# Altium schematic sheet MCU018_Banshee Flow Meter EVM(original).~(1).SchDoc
size 431 x 279 mm; Date: Not shown in title block; ApprovedBy: Not shown in title block; CheckedBy: Not shown in title block; Author: Not shown in title block; CompanyName: Not shown in title block; Engineer: Not shown in title block; Organization: Not shown in title block; Address1: Not shown in title block; Address2: Not shown in title block; Address3: Not shown in title block; Address4: Not shown in title block; DocumentNumber: 1; Revision: Use project parameter SCH_Rev; SheetNumber: 1; SheetTotal: 6; PageSetup: Record=PageOptions¦CenterHorizontal=True¦CenterVertical=True¦PrintScale=1.00¦XCorrection=1.00¦YCorrection=1.00¦PrintKind=0¦BorderSize=5000000¦LeftOffset=0¦BottomOffset=0¦Orientation=2¦PaperLength=1000¦PaperWidth=1000¦Scale=100¦PaperSource=15¦PrintQuality=600¦MediaType=1¦DitherType=10¦PaperKind=Letter¦PrintScaleMode=1
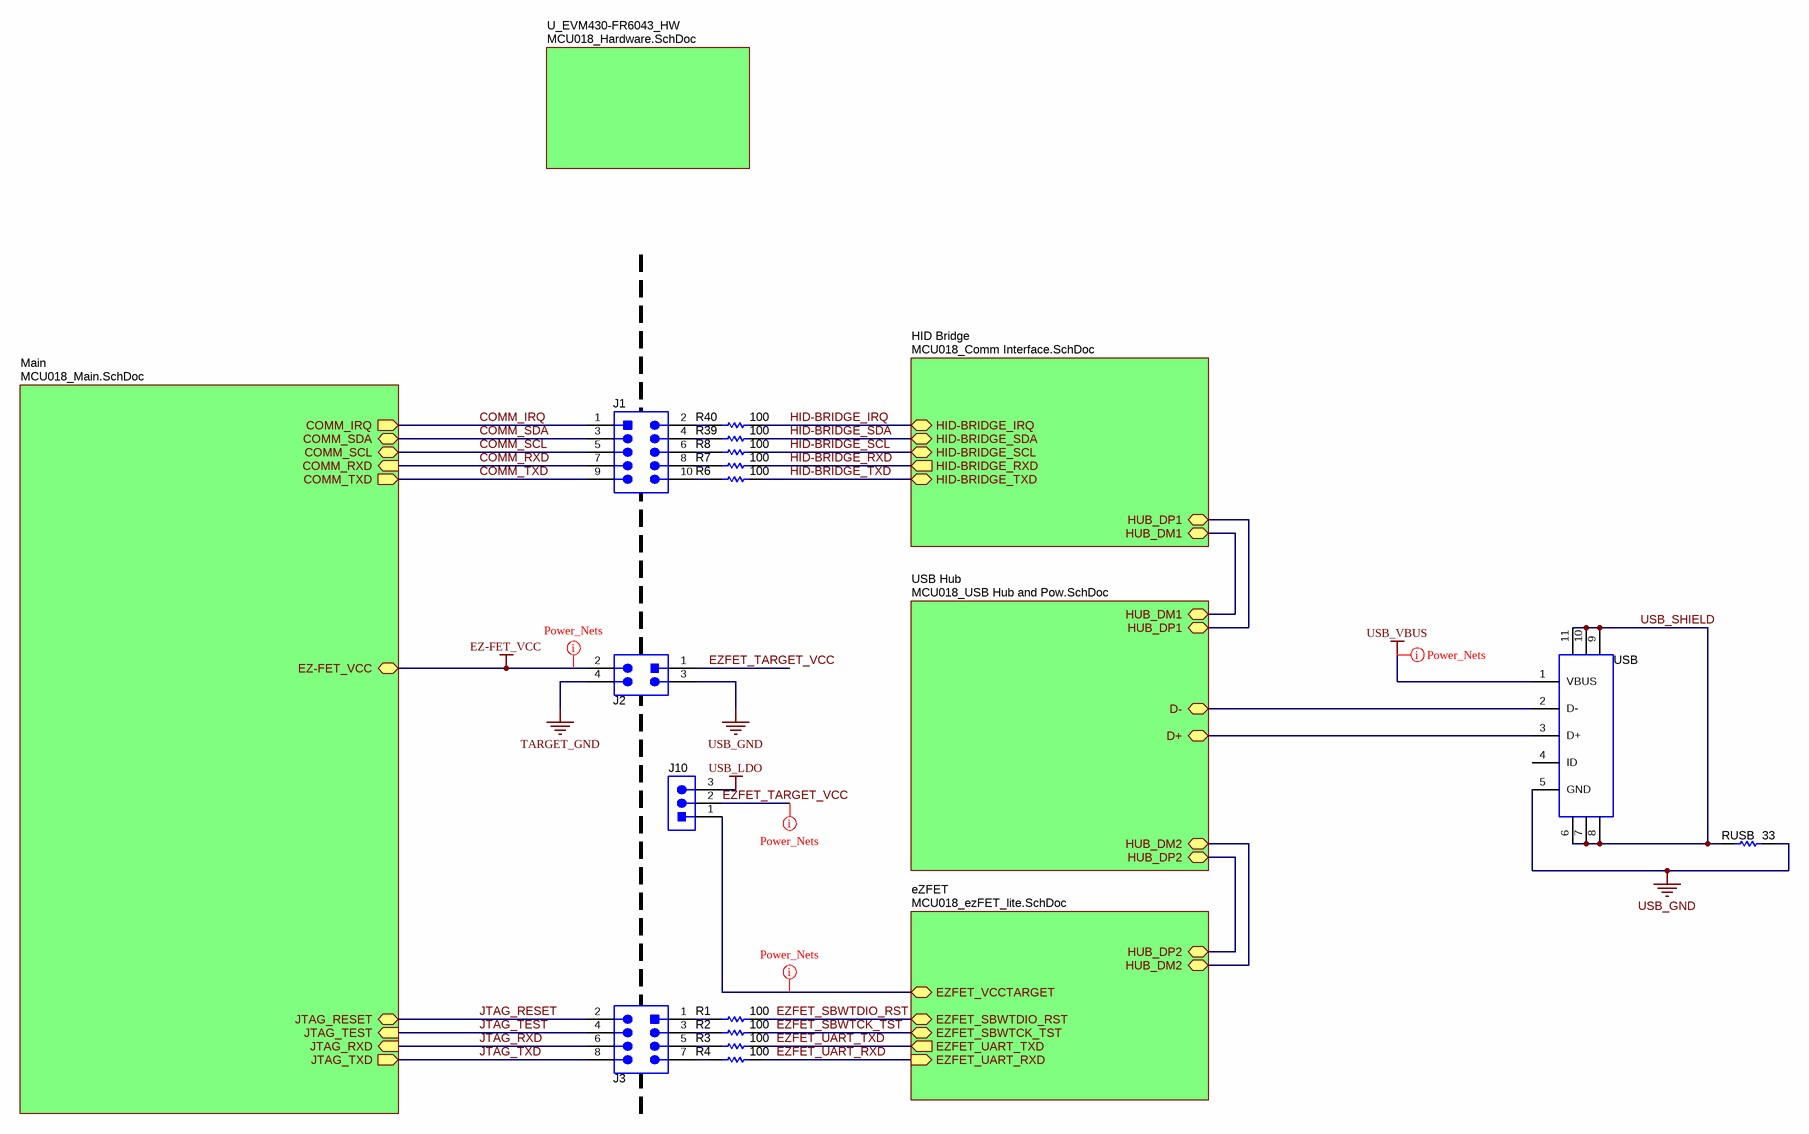
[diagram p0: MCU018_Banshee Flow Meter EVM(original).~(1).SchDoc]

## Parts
J1  61301021121  [WURTH_61301021121]  (value not drawn)
J2  PBC02DAAN  [Sullins_PxC02DAAN]  (value not drawn)
J3  PEC04DAAN  [CONN_PEC04DAAN]  (value not drawn)
J10  61300311121  [WURTH_61300311121]  (value not drawn)
R1  ValueDisplayed: 100  [0402S]  (hidden comment: CRCW0402100RJNED)
R2  ValueDisplayed: 100  [0402S]  (hidden comment: CRCW0402100RJNED)
R3  ValueDisplayed: 100  [0402S]  (hidden comment: CRCW0402100RJNED)
R4  ValueDisplayed: 100  [0402S]  (hidden comment: CRCW0402100RJNED)
R6  ValueDisplayed: 100  [0402S]  (hidden comment: CRCW0402100RJNED)
R7  ValueDisplayed: 100  [0402S]  (hidden comment: CRCW0402100RJNED)
R8  ValueDisplayed: 100  [0402S]  (hidden comment: CRCW0402100RJNED)
R39  ValueDisplayed: 100  [0402S]  (hidden comment: CRCW0402100RJNED)
R40  ValueDisplayed: 100  [0402S]  (hidden comment: CRCW0402100RJNED)
RUSB  value 33  [0402S]  (hidden comment: CRCW040233R0JNED)
USB  1051640001  [Molex_1051640001]  (value not drawn)

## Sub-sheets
eZFET = MCU018_ezFET_lite.SchDoc: EZFET_VCCTARGET, EZFET_SBWTDIO_RST, EZFET_SBWTCK_TST, EZFET_UART_TXD, EZFET_UART_RXD, HUB_DP2, HUB_DM2
HID Bridge = MCU018_Comm Interface.SchDoc: HID-BRIDGE_TXD, HID-BRIDGE_RXD, HID-BRIDGE_SCL, HID-BRIDGE_SDA, HID-BRIDGE_IRQ, HUB_DM1, HUB_DP1
Main = MCU018_Main.SchDoc: COMM_IRQ, COMM_SDA, COMM_SCL, COMM_RXD, COMM_TXD, EZ-FET_VCC, JTAG_RESET, JTAG_TEST, JTAG_RXD, JTAG_TXD
U_EVM430-FR6043_HW = MCU018_Hardware.SchDoc: no entries
USB Hub = MCU018_USB Hub and Pow.SchDoc: HUB_DM1, HUB_DP1, D-, D+, HUB_DM2, HUB_DP2

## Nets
EZ-FET_VCC: J2.2 ; sheet Main/EZ-FET_VCC
TARGET_GND: J2.4
USB_GND: J2.3 RUSB.1 USB.5(GND)
USB_LDO: J10.3
USB_VBUS: USB.1(VBUS)
COMM_IRQ: J1.1 ; sheet Main/COMM_IRQ
COMM_RXD: J1.7 ; sheet Main/COMM_RXD
COMM_SCL: J1.5 ; sheet Main/COMM_SCL
COMM_SDA: J1.3 ; sheet Main/COMM_SDA
COMM_TXD: J1.9 ; sheet Main/COMM_TXD
EZFET_SBWTCK_TST: R2.1 ; sheet eZFET/EZFET_SBWTCK_TST
EZFET_SBWTDIO_RST: R1.1 ; sheet eZFET/EZFET_SBWTDIO_RST
EZFET_TARGET_VCC: J2.1 J10.2
EZFET_UART_RXD: R4.1 ; sheet eZFET/EZFET_UART_RXD
EZFET_UART_TXD: R3.1 ; sheet eZFET/EZFET_UART_TXD
HID-BRIDGE_IRQ: R40.1 ; sheet HID Bridge/HID-BRIDGE_IRQ
HID-BRIDGE_RXD: R7.1 ; sheet HID Bridge/HID-BRIDGE_RXD
HID-BRIDGE_SCL: R8.1 ; sheet HID Bridge/HID-BRIDGE_SCL
HID-BRIDGE_SDA: R39.1 ; sheet HID Bridge/HID-BRIDGE_SDA
HID-BRIDGE_TXD: R6.1 ; sheet HID Bridge/HID-BRIDGE_TXD
JTAG_RESET: J3.2 ; sheet Main/JTAG_RESET
JTAG_RXD: J3.6 ; sheet Main/JTAG_RXD
JTAG_TEST: J3.4 ; sheet Main/JTAG_TEST
JTAG_TXD: J3.8 ; sheet Main/JTAG_TXD
USB_SHIELD: RUSB.2 USB.6 USB.7 USB.8 USB.9 USB.10 USB.11
NetJ1_2: J1.2 R40.2
NetJ1_4: J1.4 R39.2
NetJ1_6: J1.6 R8.2
NetJ1_8: J1.8 R7.2
NetJ1_10: J1.10 R6.2
NetJ3_1: J3.1 R1.2
NetJ3_3: J3.3 R2.2
NetJ3_5: J3.5 R3.2
NetJ3_7: J3.7 R4.2
NetJ10_1: J10.1 ; sheet eZFET/EZFET_VCCTARGET
NetUSB_2: USB.2(D-) ; sheet USB Hub/D-
NetUSB_3: USB.3(D+) ; sheet USB Hub/D+
(unnamed): sheet USB Hub/HUB_DM1, sheet HID Bridge/HUB_DM1
(unnamed): sheet USB Hub/HUB_DP1, sheet HID Bridge/HUB_DP1  [a separate net that carries the same name]
(unnamed): sheet USB Hub/HUB_DM2, sheet eZFET/HUB_DM2  [a separate net that carries the same name]
(unnamed): sheet USB Hub/HUB_DP2, sheet eZFET/HUB_DP2  [a separate net that carries the same name]

Not connected (* = marked no-connect by the designer): USB 4(ID)

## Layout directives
net class Power_Nets: EZ-FET_VCC, EZFET_TARGET_VCC, NetJ10_1, USB_VBUS

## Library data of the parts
J1 = 61301021121: Header, 2.54 mm, 5x2, Gold, TH; Manufacturer: Wurth Elektronik; SymbolCreator: a0412235; Green_Lifecycle: Active; Green_REACh: Passed
J2 = PBC02DAAN: Header, 2.54mm, 2x2, Gold, TH; Manufacturer: Sullins Connector Solutions; SymbolCreator: a0412235; Pitch_mm: 2.54; Gender: Male; Shrouded: N; Row_Count: 2; Current_A: 3; Voltage_V: 1800; Cert_UL: Y
J3 = PEC04DAAN: Header, 100mil, 4x2, Tin, TH; Manufacturer: Sullins Connector Solutions; SymbolCreator: a0411947; Pitch_mm: 2.54; Gender: Male; Shrouded: N; Row_Count: 2; Current_A: 3; Voltage_V: 1800; Cert_UL: Y; Green_Lifecycle: Not Set; Green_REACh: Incomplete
J10 = 61300311121: Header, 2.54 mm, 3x1, Gold, TH; Manufacturer: Wurth Elektronik; SymbolCreator: a0799628; Green_Lifecycle: Active; Green_REACh: Passed
R1-R4 R6-R8 R39 R40 = CRCW0402100RJNED: RES, 100, 5%, 0.063 W, 0402; Manufacturer: Vishay-Dale; CompType: Resistor; Value: 100; Value_Code: 100R; Tolerance_%: 5; Power_W: 0.063; Value2: 0.063W; VDC_V: 50; TempCo: 200 ppm/C; EIA_Code: E24; U/M: EA; AEC Category: Q200
RUSB = CRCW040233R0JNED: RES, 33 ohm, 5%, 0.063W, 0402; Manufacturer: Vishay-Dale; CompType: Resistor; Value_Code: 33R0; Tolerance_%: 5; Power_W: 0.063; VDC_V: 50; TempCo: 200 ppm/C; EIA_Code: E24; U/M: EA
USB = 1051640001: Receptacle, USB 2.0, Micro B, 5 Position, R/A, SMT; Manufacturer: Molex; SymbolCreator: a0411947; Pitch_mm: 0.65; Gender: Female; ContactFinish: Gold; Current_A: 1.8; Voltage_V: 30; Cert_UL: Y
